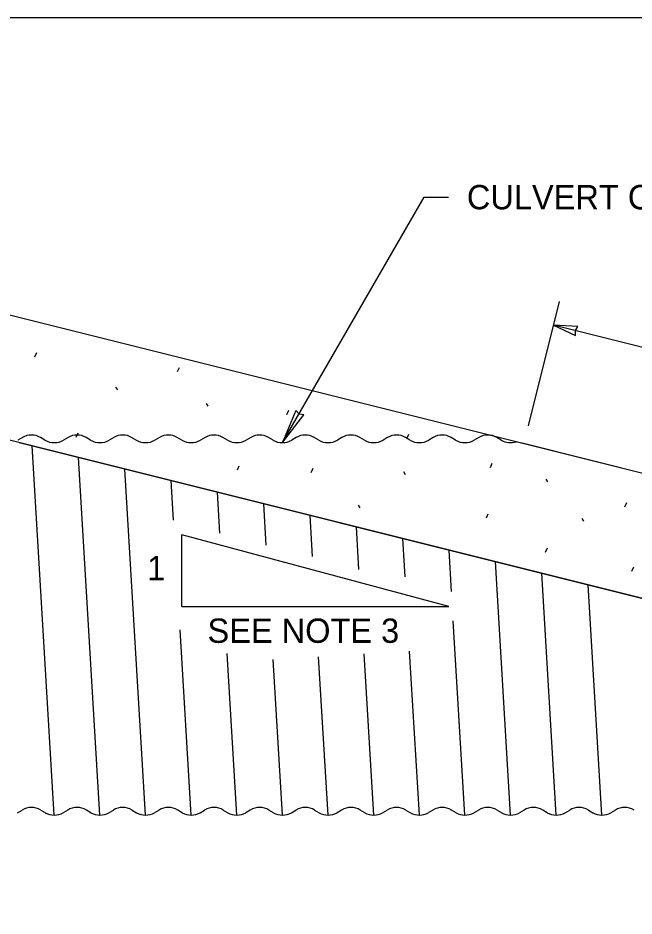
# Model space of a CAD drawing. Extents: x 99862 to 103151, y 100000 to 102076.
# Drawn here: x 100937 to 101342, y 101485 to 102076 of the extents above; entities that cross this region are included whole.
import ezdxf

# ---------------------------------------------------------------- set-up
doc = ezdxf.new("R2010")
doc.units = 0
for name, color, linetype in [('Level 1', 7, 'Continuous'), ('Level 13', 7, 'Continuous'), ('Level 15', 7, 'Continuous'), ('Level 17', 7, 'Continuous'), ('Level 20', 7, 'Continuous')]:
    doc.layers.add(name, color=color, linetype=linetype)

msp = doc.modelspace()

# ---------------------------------------------------------------- linework, layer by layer
at = {"layer": 'Level 1'}
for p, q in [((100940.25, 101799.59), (100937.26, 101797.81)), ((100940.25, 101799.59), (100937.26, 101797.81)), ((100937.26, 101797.81), (100937.26, 101797.81)), ((100938.07, 101796.13), (101898.06, 101556.13)), ((100954.98, 101797.81), (100952, 101799.59)), ((100970.25, 101799.59), (100967.26, 101797.81)), ((100984.98, 101797.81), (100982, 101799.59)), ((100984.98, 101797.81), (100982, 101799.59)), ((101000.25, 101799.59), (100997.26, 101797.81)), ((101000.25, 101799.59), (100997.26, 101797.81)), ((101014.98, 101797.81), (101012, 101799.59)), ((101030.25, 101799.59), (101027.26, 101797.81)), ((101044.98, 101797.81), (101042, 101799.59)), ((101060.25, 101799.59), (101057.26, 101797.81)), ((101074.98, 101797.81), (101072, 101799.59)), ((101090.25, 101799.59), (101087.26, 101797.81)), ((101104.98, 101797.81), (101102, 101799.59)), ((101120.25, 101799.59), (101117.26, 101797.81)), ((101134.98, 101797.81), (101132, 101799.59)), ((101150.25, 101799.59), (101147.26, 101797.81)), ((101164.98, 101797.81), (101162, 101799.59)), ((101180.25, 101799.59), (101177.26, 101797.81)), ((101194.98, 101797.81), (101192, 101799.59)), ((101210.25, 101799.59), (101207.26, 101797.81)), ((101224.98, 101797.81), (101222, 101799.59)), ((101240.25, 101799.59), (101237.26, 101797.81)), ((101254.98, 101797.81), (101252, 101799.59)), ((101267.5, 101796.13), (101472.62, 101744.77)), ((101267.92, 101796.13), (101472.66, 101744.94)), ((100961.12, 101551.13), (100946.55, 101794.01)), ((100991.12, 101551.13), (100977, 101786.39)), ((101021.12, 101551.13), (101007.46, 101778.78)), ((101039.48, 101745.09), (101037.92, 101771.16)), ((101069.99, 101736.63), (101068.38, 101763.55)), ((101100.47, 101728.66), (101098.83, 101755.93)), ((101130.92, 101721.22), (101129.29, 101748.32)), ((101161.42, 101712.78), (101159.75, 101740.71)), ((101044.93, 101688.44), (101044.93, 101735.45)), ((101220.61, 101688.44), (101044.93, 101735.45)), ((101191.71, 101707.9), (101190.2, 101733.09)), ((101222.29, 101698.3), (101220.66, 101725.48)), ((101261.12, 101551.13), (101251.12, 101717.86)), ((101291.12, 101551.13), (101281.57, 101710.25)), ((101321.12, 101551.13), (101312.03, 101702.63)), ((101044.93, 101688.44), (101220.61, 101688.44)), ((101231.12, 101551.13), (101223.45, 101678.94)), ((101051.12, 101551.13), (101043.81, 101672.9)), ((101201.12, 101551.13), (101194.65, 101658.91)), ((101081.12, 101551.13), (101074.75, 101657.34)), ((101111.12, 101551.13), (101104.98, 101653.53)), ((101141.12, 101551.13), (101134.87, 101655.32)), ((101171.12, 101551.13), (101164.76, 101657.12)), ((100937, 101552.66), (100939.98, 101554.44)), ((100952.26, 101554.44), (100955.25, 101552.66)), ((100969.98, 101554.44), (100967, 101552.66)), ((100985.25, 101552.66), (100982.26, 101554.44)), ((100997, 101552.66), (100999.98, 101554.44)), ((101012.26, 101554.44), (101015.25, 101552.66)), ((101029.98, 101554.44), (101027, 101552.66)), ((101045.25, 101552.66), (101042.26, 101554.44)), ((101057, 101552.66), (101059.98, 101554.44)), ((101072.26, 101554.44), (101075.25, 101552.66)), ((101089.98, 101554.44), (101087, 101552.66)), ((101105.25, 101552.66), (101102.26, 101554.44)), ((101117, 101552.66), (101119.98, 101554.44)), ((101132.26, 101554.44), (101135.25, 101552.66)), ((101149.98, 101554.44), (101147, 101552.66)), ((101165.25, 101552.66), (101162.26, 101554.44)), ((101177, 101552.66), (101179.98, 101554.44)), ((101192.26, 101554.44), (101195.25, 101552.66)), ((101209.98, 101554.44), (101207, 101552.66)), ((101225.25, 101552.66), (101222.26, 101554.44)), ((101237, 101552.66), (101239.98, 101554.44)), ((101252.26, 101554.44), (101255.25, 101552.66)), ((101269.98, 101554.44), (101267, 101552.66)), ((101285.25, 101552.66), (101282.26, 101554.44)), ((101297, 101552.66), (101299.98, 101554.44)), ((101312.26, 101554.44), (101315.25, 101552.66)), ((101329.98, 101554.44), (101327, 101552.66))]:
    msp.add_line(p, q, dxfattribs=at)
msp.add_lwpolyline([(99862, 99999.5), (103151, 99999.5), (103151, 102075.5), (99862, 102075.5)], close=True, dxfattribs=at)
for centre, start, end in [((100946.12, 101789.13), 90, 119.31291), ((100946.12, 101789.13), 90, 119.31291), ((100946.12, 101789.13), 60.68709, 90), ((100976.12, 101789.13), 90, 119.31291), ((100976.12, 101789.13), 60.68709, 90), ((100976.12, 101789.13), 60.68709, 90), ((101006.12, 101789.13), 90, 119.31291), ((101006.12, 101789.13), 90, 119.31291), ((101006.12, 101789.13), 60.68709, 90), ((101036.12, 101789.13), 90, 119.31291), ((101036.12, 101789.13), 60.68709, 90), ((101066.12, 101789.13), 90, 119.31291), ((101066.12, 101789.13), 60.68709, 90), ((101096.12, 101789.13), 90, 119.31291), ((101096.12, 101789.13), 60.68709, 90), ((101126.12, 101789.13), 90, 119.31291), ((101126.12, 101789.13), 60.68709, 90), ((101156.12, 101789.13), 90, 119.31291), ((101156.12, 101789.13), 60.68709, 90), ((101186.12, 101789.13), 90, 119.31291), ((101186.12, 101789.13), 60.68709, 90), ((101216.12, 101789.13), 90, 119.31291), ((101216.12, 101789.13), 60.68709, 90), ((101246.12, 101789.13), 90, 119.31291), ((101246.12, 101789.13), 60.68709, 90), ((100961.12, 101808.13), 239.24007, 300.75993), ((100991.12, 101808.13), 239.24007, 300.75993), ((100991.12, 101808.13), 239.24007, 300.75993), ((101021.12, 101808.13), 239.24007, 300.75993), ((101051.12, 101808.13), 239.24007, 300.75993), ((101081.12, 101808.13), 239.24007, 300.75993), ((101111.12, 101808.13), 239.24007, 300.75993), ((101141.12, 101808.13), 239.24007, 300.75993), ((101171.12, 101808.13), 239.24007, 300.75993), ((101201.12, 101808.13), 239.24007, 300.75993), ((101231.12, 101808.13), 239.24007, 300.75993), ((101261.12, 101808.13), 239.24007, 288.68429), ((100946.12, 101544.13), 59.24007, 120.75993), ((100961.12, 101563.13), 240.68709, 270), ((100961.12, 101563.13), 270, 299.31291), ((100976.12, 101544.13), 59.24007, 120.75993), ((100991.12, 101563.13), 240.68709, 270), ((100991.12, 101563.13), 270, 299.31291), ((101006.12, 101544.13), 59.24007, 120.75993), ((101021.12, 101563.13), 240.68709, 270), ((101021.12, 101563.13), 270, 299.31291), ((101036.12, 101544.13), 59.24007, 120.75993), ((101051.12, 101563.13), 240.68709, 270), ((101051.12, 101563.13), 270, 299.31291), ((101066.12, 101544.13), 59.24007, 120.75993), ((101081.12, 101563.13), 240.68709, 270), ((101081.12, 101563.13), 270, 299.31291), ((101096.12, 101544.13), 59.24007, 120.75993), ((101111.12, 101563.13), 240.68709, 270), ((101111.12, 101563.13), 270, 299.31291), ((101126.12, 101544.13), 59.24007, 120.75993), ((101141.12, 101563.13), 240.68709, 270), ((101141.12, 101563.13), 270, 299.31291), ((101156.12, 101544.13), 59.24007, 120.75993), ((101171.12, 101563.13), 240.68709, 270), ((101171.12, 101563.13), 270, 299.31291), ((101186.12, 101544.13), 59.24007, 120.75993), ((101201.12, 101563.13), 240.68709, 270), ((101201.12, 101563.13), 270, 299.31291), ((101216.12, 101544.13), 59.24007, 120.75993), ((101231.12, 101563.13), 240.68709, 270), ((101231.12, 101563.13), 270, 299.31291), ((101246.12, 101544.13), 59.24007, 120.75993), ((101261.12, 101563.13), 240.68709, 270), ((101261.12, 101563.13), 270, 299.31291), ((101276.12, 101544.13), 59.24007, 120.75993), ((101291.12, 101563.13), 240.68709, 270), ((101291.12, 101563.13), 270, 299.31291), ((101306.12, 101544.13), 59.24007, 120.75993), ((101321.12, 101563.13), 240.68709, 270), ((101321.12, 101563.13), 270, 299.31291), ((101336.12, 101544.13), 59.24007, 120.75993)]:
    msp.add_arc(centre, 12, start, end, dxfattribs=at)
at = {"layer": 'Level 13'}
for p, q in [((100899.26, 101888.29), (102226.12, 101556.57)), ((102146.12, 101494.11), (100879.86, 101810.68))]:
    msp.add_line(p, q, dxfattribs=at)
at = {"layer": 'Level 15'}
for p, q in [((101111.12, 101796.13), (101204.37, 101957.63)), ((101204.37, 101957.63), (101220.37, 101957.63)), ((101293.14, 101888.99), (101272.72, 101807.29)), ((101470.7, 101828.11), (101289.26, 101873.47))]:
    msp.add_line(p, q, dxfattribs=at)
for points in [[(101289.26, 101873.47), (101303.77, 101866.66), (101303.81, 101869.83), (101305.26, 101872.64)], [(101111.12, 101796.13), (101125.12, 101814.4), (101122.01, 101814.98), (101119.95, 101817.39)]]:
    msp.add_lwpolyline(points, close=True, dxfattribs=at)
at = {"layer": 'Level 17'}
for p, q in [((100948.37, 101852.68), (100949.61, 101855.45)), ((101042.14, 101842.83), (101043.45, 101845.59)), ((101001.43, 101832.71), (101002.61, 101830.91)), ((101060.87, 101821.96), (101062.05, 101820.09)), ((101114, 101814.73), (101115.24, 101817.5)), ((100975.5, 101799.74), (100976.75, 101802.51)), ((101192.99, 101798.9), (101194.3, 101801.66)), ((101081.51, 101778.16), (101082.76, 101780.92)), ((101130.06, 101776.5), (101131.31, 101779.27)), ((101247.81, 101779.76), (101249.05, 101782.53)), ((101190.61, 101777.05), (101191.79, 101775.18)), ((101284.2, 101772.2), (101285.38, 101770.4)), ((101160.81, 101755.12), (101161.99, 101753.32)), ((101336.2, 101753.93), (101337.51, 101756.69)), ((101245.19, 101746.59), (101246.44, 101749.35)), ((101307.85, 101746.25), (101309.03, 101744.38)), ((101284.16, 101724.09), (101285.41, 101726.86)), ((101340.83, 101711.59), (101342.08, 101714.35))]:
    msp.add_line(p, q, dxfattribs=at)

# ---------------------------------------------------------------- texts
at = {"layer": 'Level 20'}
for s, p in [('CULVERT CROWN', (101232.37, 101949.63)), ('1', (101022.15, 101705.62)), ('SEE NOTE 3', (101061.86, 101664.44))]:
    msp.add_text(s, height=16, dxfattribs=at).set_placement(p)

doc.saveas('drawing.dxf')
